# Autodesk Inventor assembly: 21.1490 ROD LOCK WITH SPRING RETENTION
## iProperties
Created: 2012-03
Part Number: 21.1490 ROD LOCK WITH SPRING RETENTION
Document SubType Name: Assembly
Designer: Administrator
Author: Administrator
